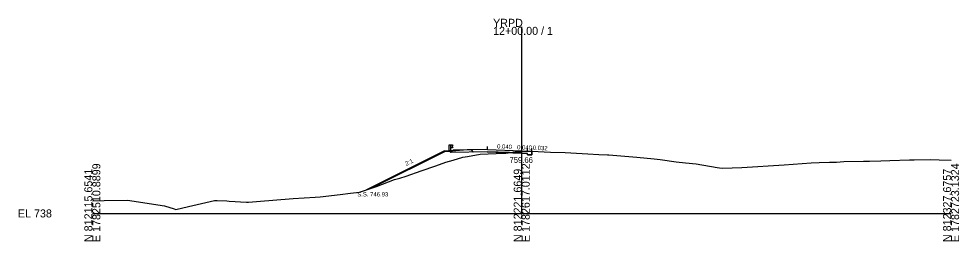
# Model space of a CAD drawing. Extents: x -26 to 1403, y -10 to 9544.
# Drawn here: x -25.7 to 302.8, y 1990.3 to 2068 of the extents above; entities that cross this region are included whole.
import ezdxf

# ---------------------------------------------------------------- set-up
doc = ezdxf.new("R2010")
doc.units = 0
for name, color, linetype in [('Exist Cross Section Cell', 7, 'Continuous'), ('Exist XS Center Line Elevation Label', 7, 'Continuous'), ('Exist XS Ground Line', 7, 'Continuous'), ('Prop XS Dump Level', 7, 'Continuous'), ('Prop XS Earthwork Shape', 7, 'Continuous'), ('Prop XS EOT Tick Mark', 7, 'Continuous'), ('Prop XS Finish Grade', 7, 'Continuous'), ('Prop XS Finish Grade Earthwork', 7, 'Continuous'), ('Prop XS Finish Grade Paved Shoulder', 7, 'Continuous'), ('Prop XS Finish Grade Pavement', 7, 'Continuous'), ('Prop XS Guardrail', 7, 'Continuous'), ('Prop XS Pvmt Edge Slope', 7, 'Continuous'), ('Prop XS SE Text', 7, 'Continuous'), ('Prop XS Side Slope Text', 7, 'Continuous'), ('Prop XS SS Elevation Text', 7, 'Continuous'), ('Prop XS Subgrade Earthwork', 7, 'Continuous')]:
    doc.layers.add(name, color=color, linetype=linetype)

msp = doc.modelspace()

# ---------------------------------------------------------------- linework, layer by layer
at = {"layer": 'Exist Cross Section Cell'}
for p, q in [((150, 2000), (150, 2065.17)), ((0, 2000), (150, 2000)), ((150, 2000), (300, 2000))]:
    msp.add_line(p, q, dxfattribs=at)
at = {"layer": 'Exist XS Ground Line'}
for p, q in [((131.12, 2019.89), (135.47, 2020.71)), ((135.47, 2020.71), (141.07, 2020.97)), ((141.07, 2020.97), (144.4, 2021.09)), ((144.4, 2021.09), (148.71, 2021.58)), ((148.71, 2021.58), (149.35, 2021.65)), ((149.35, 2021.65), (150, 2021.66)), ((150, 2021.66), (153.58, 2021.72)), ((153.58, 2021.72), (160.08, 2021.45)), ((160.08, 2021.45), (165.13, 2021.24)), ((165.13, 2021.24), (173.05, 2020.83)), ((173.05, 2020.83), (176.94, 2020.63)), ((176.94, 2020.63), (179.92, 2020.46)), ((120.02, 2016.64), (123.48, 2017.86)), ((123.48, 2017.86), (126.09, 2018.66)), ((126.09, 2018.66), (129.45, 2019.6)), ((129.45, 2019.6), (131.12, 2019.89)), ((179.92, 2020.46), (180.44, 2020.43)), ((180.44, 2020.43), (190.25, 2019.67)), ((190.25, 2019.67), (196.27, 2019.03)), ((196.27, 2019.03), (198.35, 2018.79)), ((198.35, 2018.79), (203.96, 2018.08)), ((203.96, 2018.08), (207.23, 2017.71)), ((207.23, 2017.71), (210.93, 2017.28)), ((210.93, 2017.28), (218.29, 2016.09)), ((241.67, 2016.93), (251.08, 2017.64)), ((251.08, 2017.64), (253.88, 2017.77)), ((253.88, 2017.77), (257.49, 2017.85)), ((257.49, 2017.85), (260.01, 2017.93)), ((260.01, 2017.93), (262.56, 2018.12)), ((262.56, 2018.12), (269.46, 2018.26)), ((269.46, 2018.26), (271.49, 2018.31)), ((271.49, 2018.31), (275.52, 2018.32)), ((275.52, 2018.32), (278.66, 2018.51)), ((278.66, 2018.51), (285.52, 2018.77)), ((285.52, 2018.77), (287.16, 2018.73)), ((287.16, 2018.73), (292.71, 2018.84)), ((292.71, 2018.84), (295.84, 2018.75)), ((295.84, 2018.75), (300, 2018.6)), ((109.59, 2013.04), (114.87, 2014.92)), ((114.87, 2014.92), (120.02, 2016.64)), ((218.29, 2016.09), (219.07, 2015.91)), ((219.07, 2015.91), (220.16, 2015.86)), ((220.16, 2015.86), (226.86, 2016.01)), ((226.86, 2016.01), (241.67, 2016.93)), ((99.29, 2009.46), (105.53, 2011.85)), ((105.53, 2011.85), (107.46, 2012.33)), ((107.46, 2012.33), (109.59, 2013.04)), ((90.24, 2007.03), (93.34, 2007.4)), ((93.34, 2007.4), (99.29, 2009.46)), ((0, 2004.4), (4.09, 2004.49)), ((4.09, 2004.49), (12.3, 2004.65)), ((12.3, 2004.65), (25.18, 2002.63)), ((33.63, 2002.46), (42.68, 2004.56)), ((42.68, 2004.56), (43.56, 2004.55)), ((43.56, 2004.55), (46.98, 2004.42)), ((46.98, 2004.42), (47.85, 2004.33)), ((47.85, 2004.33), (49.94, 2004.19)), ((49.94, 2004.19), (51.72, 2004.07)), ((51.72, 2004.07), (53.88, 2003.91)), ((54.61, 2003.96), (57.3, 2004.15)), ((57.3, 2004.15), (70.11, 2005.17)), ((70.11, 2005.17), (77.84, 2005.69)), ((77.84, 2005.69), (79.56, 2005.82)), ((79.56, 2005.82), (86.54, 2006.59)), ((86.54, 2006.59), (90.24, 2007.03)), ((25.18, 2002.63), (28.62, 2001.58)), ((28.62, 2001.58), (29.12, 2001.35)), ((29.12, 2001.35), (33.63, 2002.46)), ((53.88, 2003.91), (54.61, 2003.96))]:
    msp.add_line(p, q, dxfattribs=at)
at = {"layer": 'Prop XS Dump Level'}
for p, q in [((138, 2022.34), (150, 2021.86)), ((150, 2021.86), (152, 2021.78))]:
    msp.add_line(p, q, dxfattribs=at)
at = {"layer": 'Prop XS Earthwork Shape'}
for points in [[(97.75, 2008.93), (99.29, 2009.46), (105.53, 2011.85), (107.46, 2012.33), (109.59, 2013.04), (114.87, 2014.92), (120.02, 2016.64), (123.48, 2017.86), (126.09, 2018.66), (129.45, 2019.6), (131.12, 2019.89), (135.47, 2020.71), (141.07, 2020.97), (144.4, 2021.09), (145.69, 2021.24), (137.99, 2021.54), (133.19, 2021.45), (132.42, 2022.22), (131, 2022.2), (123, 2021.56)], [(145.69, 2021.24), (148.71, 2021.58), (149.35, 2021.65), (150, 2021.66), (153.58, 2021.72), (153.58, 2020.47), (152, 2020.52), (152, 2020.98), (149.97, 2021.06)]]:
    msp.add_lwpolyline(points, close=True, dxfattribs=at)
at = {"layer": 'Prop XS EOT Tick Mark'}
for p, q in [((138, 2022.34), (138, 2023.34)), ((152, 2021.78), (152, 2022.78)), ((153.58, 2021.72), (153.58, 2022.72))]:
    msp.add_line(p, q, dxfattribs=at)
at = {"layer": 'Prop XS Finish Grade'}
msp.add_line((124.5, 2021.98), (126, 2022.1), dxfattribs=at)
at = {"layer": 'Prop XS Finish Grade Earthwork'}
for q in [(95.8, 2008.26), (124.5, 2021.98)]:
    msp.add_line((123, 2021.86), q, dxfattribs=at)
at = {"layer": 'Prop XS Finish Grade Paved Shoulder'}
for p, q in [((138, 2022.34), (126, 2022.1)), ((152, 2021.78), (153.58, 2021.72))]:
    msp.add_line(p, q, dxfattribs=at)
at = {"layer": 'Prop XS Finish Grade Pavement'}
for p, q in [((138, 2022.34), (150, 2021.86)), ((150, 2021.86), (152, 2021.78))]:
    msp.add_line(p, q, dxfattribs=at)
at = {"layer": 'Prop XS Guardrail'}
for p, q in [((124.68, 2024.01), (125.18, 2024.01)), ((124.68, 2021.51), (124.68, 2024.01)), ((125.18, 2024.01), (125.68, 2024.01)), ((125.18, 2024.01), (125.18, 2021.51)), ((125.68, 2024.01), (125.97, 2023.81)), ((125.97, 2023.81), (126, 2023.75)), ((125.68, 2022.88), (125.18, 2022.88)), ((125.97, 2023.69), (125.68, 2023.49)), ((125.68, 2023.49), (125.68, 2023.4)), ((125.68, 2023.4), (125.97, 2023.2)), ((125.97, 2023.08), (125.68, 2022.88)), ((126, 2023.75), (125.97, 2023.69)), ((125.97, 2023.2), (126, 2023.14)), ((126, 2023.14), (125.97, 2023.08))]:
    msp.add_line(p, q, dxfattribs=at)
at = {"layer": 'Prop XS Pvmt Edge Slope'}
msp.add_line((126, 2022.1), (125.19, 2021.29), dxfattribs=at)
at = {"layer": 'Prop XS Subgrade Earthwork'}
for p, q in [((125.19, 2021.29), (124.5, 2021.98)), ((137.99, 2021.54), (125.19, 2021.29)), ((137.99, 2021.54), (149.97, 2021.06)), ((149.97, 2021.06), (152, 2020.98)), ((152, 2020.52), (152, 2020.98)), ((152, 2020.52), (153.58, 2020.47)), ((153.58, 2020.47), (153.58, 2021.72))]:
    msp.add_line(p, q, dxfattribs=at)

# ---------------------------------------------------------------- texts
at = {"layer": 'Exist Cross Section Cell'}
for s, p in [('YRPD', (140, 2065.17)), ('12+00.00 / 1', (140, 2062.37)), ('EL 738', (-26, 1998.6))]:
    msp.add_text(s, height=2.8, dxfattribs=at).set_placement(p)
for s, p in [('E 1782510.8899', (2.8, 1990)), ('E 1782617.0112', (152.8, 1990)), ('E 1782723.1324', (302.8, 1990)), ('N 812115.6541', (0, 1990)), ('N 812221.6649', (150, 1990)), ('N 812327.6757', (300, 1990))]:
    msp.add_text(s, height=2.8, rotation=90, dxfattribs=at).set_placement(p)
at = {"layer": 'Exist XS Center Line Elevation Label'}
msp.add_text('759.66', height=2, dxfattribs=at).set_placement((145.73, 2017.66))
at = {"layer": 'Prop XS Dump Level'}
msp.add_text('Case4', height=0.04, dxfattribs=at).set_placement((126, 2021.76))
at = {"layer": 'Prop XS SE Text'}
for s, p in [('0.040', (141.38, 2022.7)), ('0.040', (148.38, 2022.42)), ('0.032', (153.84, 2022.23))]:
    msp.add_text(s, height=1.5, rotation=357.7094, dxfattribs=at).set_placement(p)
at = {"layer": 'Prop XS Side Slope Text'}
msp.add_text('2:1', height=1.5, rotation=26.5651, dxfattribs=at).set_placement((109.71, 2016.59))
at = {"layer": 'Prop XS SS Elevation Text'}
msp.add_text('S.S. 746.93', height=1.5, dxfattribs=at).set_placement((92.56, 2005.93))

doc.saveas('drawing.dxf')
